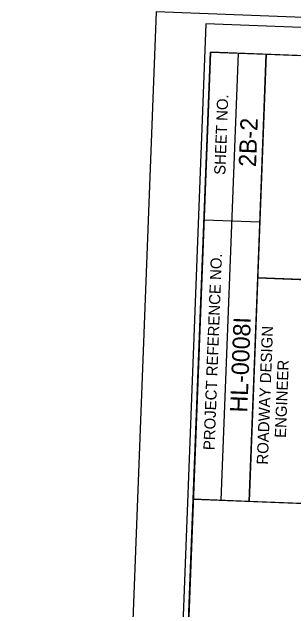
# Model space of a CAD drawing. Extents: x 2097521 to 2097987, y 686521 to 687299.
# Drawn here: x 2097521.5 to 2097571.8, y 687104.4 to 687211.1 of the extents above; entities that cross this region are included whole.
import ezdxf

# ---------------------------------------------------------------- set-up
doc = ezdxf.new("R2010")
doc.units = 0
for name, color, linetype in [('Sheet Data Field CELL', 7, 'Continuous'), ('Sheet Layout Plan Border', 7, 'Continuous'), ('Sheet Plot Border Inside CELL', 7, 'Continuous'), ('Sheet Plot Border Outside CELL', 7, 'Continuous'), ('Sheet Profile CELL', 7, 'Continuous')]:
    doc.layers.add(name, color=color, linetype=linetype)

msp = doc.modelspace()

# ---------------------------------------------------------------- linework, layer by layer
at = {"layer": 'Sheet Layout Plan Border'}
msp.add_lwpolyline([(2097534.78, 686624.29), (2097553.94, 687123.99), (2097611.01, 687121.8), (2097611.07, 687123.23), (2097798.3, 687116.05), (2097794.51, 687017.17), (2097779.16, 686617.13)], close=True, dxfattribs=at)
at = {"layer": 'Sheet Plot Border Inside CELL'}
msp.add_lwpolyline([(2097952.36, 686526.7), (2097977.91, 687192.81), (2097556.18, 687208.99), (2097530.63, 686542.88)], close=True, dxfattribs=at)
at = {"layer": 'Sheet Plot Border Outside CELL'}
msp.add_lwpolyline([(2097961.14, 686521.16), (2097986.95, 687194.27), (2097547.28, 687211.13), (2097521.46, 686538.02)], close=True, dxfattribs=at)
at = {"layer": 'Sheet Profile CELL'}
for p, q in [((2097558.96, 687123.8), (2097562.02, 687203.76)), ((2097555.88, 687173.97), (2097565.87, 687173.59)), ((2097565.49, 687163.6), (2097610.43, 687161.87))]:
    msp.add_line(p, q, dxfattribs=at)
for points in [[(2097557.01, 687203.95), (2097534.01, 686604.39), (2097953.71, 686588.3), (2097976.7, 687187.85)], [(2097553.94, 687123.99), (2097557.01, 687203.95), (2097567.02, 687203.57), (2097563.95, 687123.61)], [(2097565.49, 687163.6), (2097567.02, 687203.57), (2097611.99, 687201.84), (2097610.45, 687161.87)], [(2097563.95, 687123.61), (2097565.49, 687163.6), (2097610.45, 687161.87), (2097608.92, 687121.88)]]:
    msp.add_lwpolyline(points, close=True, dxfattribs=at)

# ---------------------------------------------------------------- texts
at = {"layer": 'Sheet Data Field CELL'}
for s, p in [('2B-2', (2097565.18, 687183.37)), ('HL-0008I', (2097563.62, 687139.46))]:
    msp.add_text(s, height=3.1, rotation=87.8037, dxfattribs=at).set_placement(p)
at = {"layer": 'Sheet Profile CELL'}
for s, p in [('SHEET NO.', (2097559.68, 687181.96)), ('PROJECT REFERENCE NO.', (2097557.75, 687132.73)), ('ROADWAY DESIGN', (2097567.3, 687130.15)), ('ENGINEER', (2097570.53, 687134.93))]:
    msp.add_text(s, height=2, rotation=87.8037, dxfattribs=at).set_placement(p)

doc.saveas('drawing.dxf')
